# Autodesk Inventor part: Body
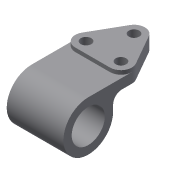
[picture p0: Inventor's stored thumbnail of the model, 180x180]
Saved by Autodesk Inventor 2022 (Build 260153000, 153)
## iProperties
Created: 2010-03
Part Number: Body
Document SubType Name: Modeling
Designer: bhakira
Density: 1 g/cm^3
Material: Generic
Appearance: Default
Author: bhakira
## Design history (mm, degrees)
sketch "Sketch1"
  geometry: L1 (10.853, 41.202)-(30.853, 6.202); L2 (-10.853, 41.202)-(-30.853, 6.202); L3 (-20, -12.5)-(20, -12.5); C1 r 6 at (0, 35); A1 r 12.5 centre (0, 35) between (10.853, 41.202) and (-10.853, 41.202); A2 r 12.5 centre (-20, 0) between (-30.853, 6.202) and (-20, -12.5); A3 r 12.5 centre (20, 0) between (20, -12.5) and (30.853, 6.202); 1 further point
  constraints: 6 end point, 6 point on circle, 6 tangent, 4 centre point, 3 horizontal alignment, 2 equal radius, 1 coincident, 1 vertical alignment, 1 other
  dimensions: "d25" = 35 vertical distance of A1.centre A2.centre; "d27" = 12.5 radius of A1; "d28" = 40 distance of A3.centre A2.centre; "d29" = 20 horizontal distance of A3.centre A1.centre
extrude "Extrusion1" new body sketch "Sketch1" distance "d6" = 16; taper "d7" = 0 deg
workplane "Work Plane2"
workplane "Work Plane3"
sketch "Sketch2"
  geometry: L1 (0, 11.5)-(0, 0); L2 (-12.5, 16)-(6.202, 16) reference; L3 (-50, 11.5)-(0, 11.5); L4 (0, 0)-(-21.5, 0); L5 (-21.5, -17)-(-21.5, 0); L6 (-12.5, 0)-(-12.5, 16) reference; C1 r 19 at (-50, -17); A1 r 28.5 centre (-50, -17) between (-50, 11.5) and (-21.5, -17)
  constraints: 8 end point, 2 centre point, 2 horizontal, 2 point on circle, 2 tangent, 1 coincident, 1 perpendicular, 1 vertical
  dimensions: "d9" = 38 diameter of C1; "d10" = 57 diameter of A1; "d11" = 50 distance from line of L1 C1.centre; "d12" = 33 distance from line of C1.centre L2
extrude "Extrusion2" join sketch "Sketch2" stored distance "d14" = 63.5; taper "d15" = 0 deg
sketch "Sketch3"
  geometry: C1 r 6 at (20, 0) reference; C2 r 6 at (-20, 0) reference; C3 r 6 at (0, 35); 1 further point
  constraints: 1 centre point
extrude "Extrusion3" cut sketch "Sketch3" distance "d16" = 63.5; taper "d17" = 0 deg
node "Sketch4"
hole "Hole1" diameter "d32" = 12; stored, may be unused: countersink angle "d36" = 90 deg, drill point angle "d38" = 118 deg; dims "d33" = 6, "d34" = 4, "d35" = 2082.8, "d37" = 8, "d39" = 10, "d40" = 10
fillet "Fillet1" dims "d42" = 10
body "Solid1"
